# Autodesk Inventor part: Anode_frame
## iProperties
Shininess: 64.0
Length Units: 11269
Angle Units: 11279
Time Units: 11290
Mass Units: 11283
Length Display Precision: 3
Angle Display Precision: 2
Compacted: True
Part Number: Anode_frame
Document SubType Name: Modeling
Created: 2003-02
Material: Standard
Designer: hofer_a
Density: 0.0
Volumn: 0.0
Area: 0.0
PropertySet Name: Model Information
Control State: 0
Master: False
Checked Out: False
Author: hofer_a
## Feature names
1. Extrusion1
2. Bohrung1 [Hole]
3. Extrusion2
4. Extrusion3
5. Rundung1 [Fillet]
6. Bohrung2 [Hole]
7. Extrusion5
8. Extrusion6
9. Bohrung3 [Hole]
10. Extrusion7
11. Extrusion8
12. Extrusion12
13. Extrusion13
